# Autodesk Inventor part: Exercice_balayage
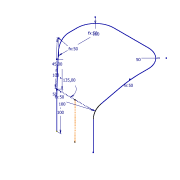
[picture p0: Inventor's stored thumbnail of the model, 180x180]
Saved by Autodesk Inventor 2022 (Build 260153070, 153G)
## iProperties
Created: 2021-06
Part Number: Exercice_balayage
Material: Générique
Document SubType Name: Modeling
Designer: Fabian
Density: 1 g/cm^3
Appearance: Par défaut
Author: Fabian
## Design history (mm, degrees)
sketch "Esquisse 3D1" dims "d9" = 100, "d11" = 100, "d12" = 45 deg, "d13" = 100, "d14" = 0, "d15" = 45 deg (derived), "d17" = 50, "d18" = 50 (= d17), "d22" = 50 (= d24), "d23" = 50 (= d24), "d24" = 50, "d25" = 50 (= d24), "d26" = 100
  node "Plan de construction1"
node "Solide1"
